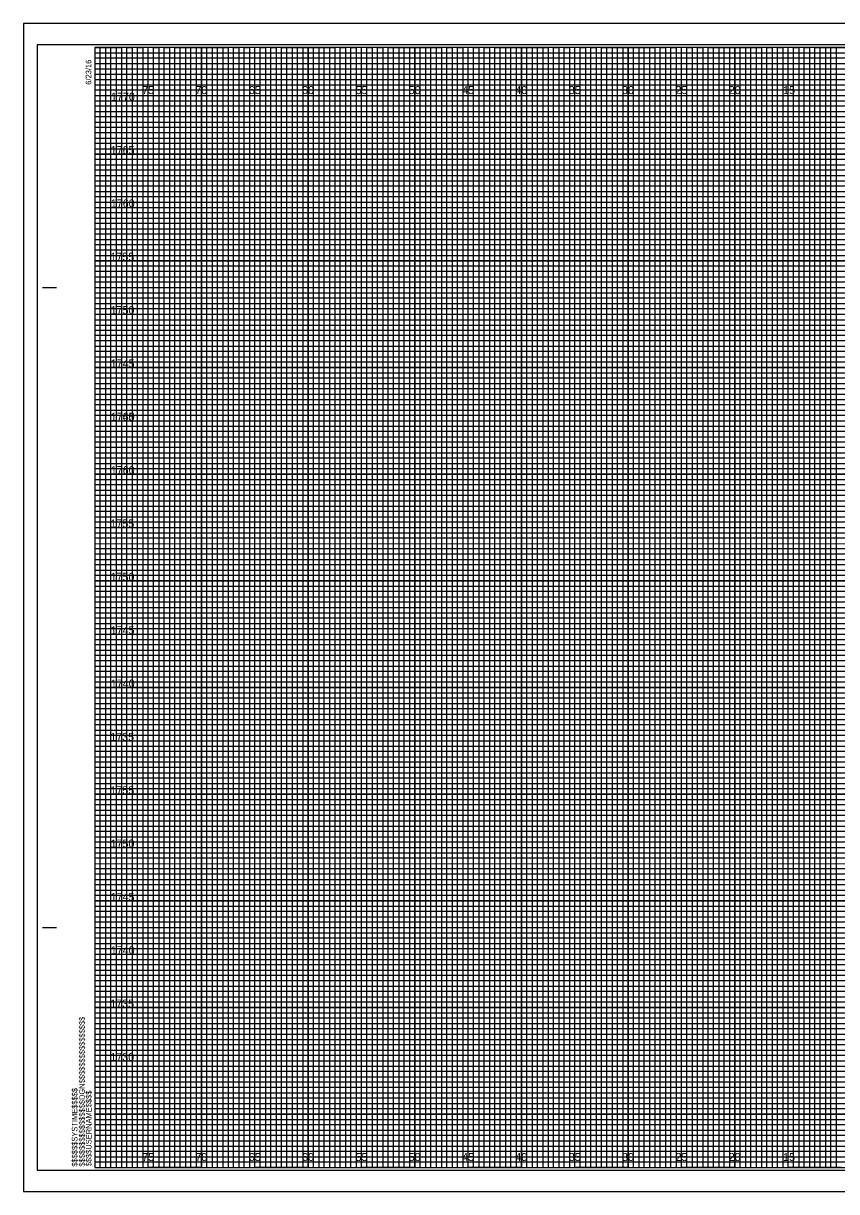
# Model space of a CAD drawing. Extents: x -7 to 162, y -2 to 217.
# Drawn here: x -6.7 to 69.5, y -2.3 to 107.3 of the extents above; entities that cross this region are included whole.
import ezdxf

# ---------------------------------------------------------------- set-up
doc = ezdxf.new("R2010")
doc.units = 0
for name, color, linetype in [('Raster_Level_0', 7, 'Continuous'), ('Scratch_Level_3', 7, 'Continuous'), ('Sheet Cross Section CELL', 7, 'Continuous'), ('Sheet Cross Section Grid Major CELL', 7, 'Continuous'), ('Sheet Cross Section Grid Middle CELL', 7, 'Continuous'), ('Sheet Cross Section Grid Minor 1 CELL', 7, 'Continuous'), ('Sheet Cross Section Grid Minor 2 CELL', 7, 'Continuous'), ('Sheet Cutting Line CELL', 7, 'Continuous'), ('Sheet DOT Grid CELL', 7, 'Continuous'), ('Sheet Plot Border Inside CELL', 7, 'Continuous'), ('Sheet Plot Border Outside CELL', 7, 'Continuous')]:
    doc.layers.add(name, color=color, linetype=linetype)

msp = doc.modelspace()

# ---------------------------------------------------------------- linework, layer by layer
at = {"layer": 'Sheet Cross Section CELL'}
for p, q in [((-4.9, 82.5), (-3.65, 82.5)), ((-4.85, 82.5), (-3.6, 82.5)), ((-4.9, 22.5), (-3.65, 22.5)), ((-4.85, 22.5), (-3.6, 22.5)), ((0, 0), (0, 0)), ((0, 0), (0, 0)), ((0, 0), (0, 0)), ((0, 0), (0, 0)), ((0, 0), (0, 0)), ((0, 0), (0, 0)), ((0, 0), (0, 0))]:
    msp.add_line(p, q, dxfattribs=at)
msp.add_lwpolyline([(160, 105), (0, 105), (0, 0), (160, 0)], close=True, dxfattribs=at)
at = {"layer": 'Sheet Cross Section Grid Major CELL'}
for p, q in [((5, 105), (0, 105)), ((5, 0), (5, 105)), ((15, 105), (10, 105)), ((10, 105), (10, 0)), ((15, 0), (15, 105)), ((25, 105), (20, 105)), ((20, 105), (20, 0)), ((25, 0), (25, 105)), ((35, 105), (30, 105)), ((30, 105), (30, 0)), ((35, 0), (35, 105)), ((45, 105), (40, 105)), ((40, 105), (40, 0)), ((45, 0), (45, 105)), ((55, 105), (50, 105)), ((50, 105), (50, 0)), ((55, 0), (55, 105)), ((65, 105), (60, 105)), ((60, 105), (60, 0)), ((65, 0), (65, 105)), ((10, 0), (5, 0)), ((20, 0), (15, 0)), ((30, 0), (25, 0)), ((40, 0), (35, 0)), ((50, 0), (45, 0)), ((60, 0), (55, 0)), ((70, 0), (65, 0))]:
    msp.add_line(p, q, dxfattribs=at)
for points in [[(0, 100), (160, 100), (160, 95), (0, 95)], [(0, 90), (160, 90), (160, 85), (0, 85)], [(0, 80), (160, 80), (160, 75), (0, 75)], [(0, 70), (160, 70), (160, 65), (0, 65)], [(0, 60), (160, 60), (160, 55), (0, 55)], [(0, 50), (160, 50), (160, 45), (0, 45)], [(0, 40), (160, 40), (160, 35), (0, 35)], [(0, 30), (160, 30), (160, 25), (0, 25)], [(0, 20), (160, 20), (160, 15), (0, 15)], [(0, 10), (160, 10), (160, 5), (0, 5)]]:
    msp.add_lwpolyline(points, dxfattribs=at)
at = {"layer": 'Sheet Cross Section Grid Middle CELL'}
for points in [[(0, 105), (2.5, 105), (2.5, 0), (7.5, 0), (7.5, 105), (12.5, 105), (12.5, 0), (17.5, 0), (17.5, 105), (22.5, 105), (22.5, 0), (27.5, 0), (27.5, 105), (32.5, 105), (32.5, 0), (37.5, 0), (37.5, 105), (42.5, 105), (42.5, 0), (47.5, 0), (47.5, 105), (52.5, 105), (52.5, 0), (57.5, 0), (57.5, 105), (62.5, 105), (62.5, 0), (67.5, 0), (67.5, 105), (72.5, 105)], [(0, 102.5), (137.5, 102.5)], [(0, 92.5), (160, 92.5), (160, 97.5), (0, 97.5)], [(0, 82.5), (160, 82.5), (160, 87.5), (0, 87.5)], [(0, 72.5), (160, 72.5), (160, 77.5), (0, 77.5)], [(0, 62.5), (160, 62.5), (160, 67.5), (0, 67.5)], [(0, 52.5), (160, 52.5), (160, 57.5), (0, 57.5)], [(0, 42.5), (160, 42.5), (160, 47.5), (0, 47.5)], [(0, 32.5), (160, 32.5), (160, 37.5), (0, 37.5)], [(0, 22.5), (160, 22.5), (160, 27.5), (0, 27.5)], [(0, 12.5), (160, 12.5), (160, 17.5), (0, 17.5)], [(0, 2.5), (160, 2.5), (160, 7.5), (0, 7.5)]]:
    msp.add_lwpolyline(points, dxfattribs=at)
at = {"layer": 'Sheet Cross Section Grid Minor 1 CELL'}
for p, q in [((0, 104.5), (130, 104.5)), ((130, 103.99), (0, 103.99)), ((0, 103.99), (0, 103.5)), ((0, 103.5), (130, 103.5)), ((130, 102.95), (0, 102.95)), ((0, 102.95), (0, 102)), ((0, 102), (160, 102))]:
    msp.add_line(p, q, dxfattribs=at)
for points in [[(0, 101.5), (135, 101.5), (160, 101.5), (160, 101), (0, 101)], [(0, 100.5), (160, 100.5), (160, 99.5), (0, 99.5)], [(0, 99), (160, 99), (160, 98.5), (0, 98.49)], [(0, 98), (160, 98), (160, 97), (0, 97)], [(0, 96.5), (160, 96.5), (160, 96), (0, 96)], [(0, 95.5), (160, 95.5), (160, 94.5), (0, 94.5)], [(0, 94), (160, 94), (160, 93.5), (0, 93.5)], [(0, 93), (160, 93), (160, 92), (0, 92)], [(0, 91.5), (160, 91.5), (160, 91), (0, 91)], [(0, 90.5), (160, 90.5), (160, 89.5), (0, 89.5)], [(0, 89), (160, 89), (160, 88.5), (0, 88.5)], [(0, 88), (160, 88), (160, 86.98), (160, 86.5), (160, 86), (0, 86)], [(0, 87), (160, 87), (160, 86.5), (0, 86.5)], [(0, 85.5), (160, 85.5), (160, 84.5), (0, 84.52)], [(0, 84.52), (160, 84.5), (160, 84), (0, 84)], [(0, 83.5), (160, 83.5), (160, 83), (0, 83)], [(0, 82), (160, 82), (160, 81.5), (0, 81.5)], [(0, 81), (160, 81), (160, 80.5), (0, 80.5)], [(-0.04, 79.45), (160, 79.45), (160, 78.94), (-0.04, 78.94)], [(0, 78.5), (160, 78.5), (160, 78), (0, 78)], [(0, 77), (160, 77), (160, 76.5), (0, 76.5)], [(0, 76), (160, 76), (160, 75.5), (0, 75.5)], [(0, 74.5), (160, 74.5), (160, 74), (0, 74)], [(0, 73.5), (160, 73.5), (160, 73), (0, 73)], [(0, 72), (160, 72), (160, 71.5), (0, 71.5)], [(0, 71), (160, 71), (160, 70.5), (0, 70.5)], [(0, 69.5), (160, 69.5), (160, 68.99), (0, 69)], [(0, 68.5), (160, 68.5), (160, 68), (0, 68)], [(0, 67), (160, 67), (160, 66.5), (0, 66.5)], [(0, 66), (160, 66), (160, 65.5), (0, 65.5)], [(0, 64.5), (160, 64.5), (160, 64), (0, 64)], [(0, 63.5), (160, 63.5), (160, 63), (0, 63)], [(0, 62), (160, 62), (160, 61.5), (0, 61.5)], [(0, 61), (160, 61), (160, 60.5), (0, 60.5)], [(0, 59.5), (160, 59.5), (160, 59), (0, 59)], [(0, 58.5), (160.03, 58.45), (160, 58), (0, 58)], [(0, 57), (160, 57), (160, 56.5), (0, 56.5)], [(0, 56), (160, 56), (160, 55.5), (0, 55.5)], [(0, 54.5), (160, 54.5), (160, 54), (0, 54)], [(0, 53.5), (160, 53.5), (160, 53), (0, 53)], [(0, 52), (160, 52), (160, 51.5), (0, 51.5)], [(0, 51), (160, 51), (160, 50.5), (0, 50.5)], [(0, 49.5), (160, 49.5), (160, 49), (0, 49)], [(0, 48.5), (160, 48.5), (160, 48), (0, 48)], [(0, 47), (160, 47), (160, 46.5), (0, 46.5)], [(0, 46), (160, 46), (160, 45.5), (0, 45.5)], [(0, 44.5), (160, 44.5), (160, 44), (0, 44)], [(0, 43.5), (160, 43.5), (160, 43), (0, 43)], [(0, 42), (160, 42), (160, 41.5), (0, 41.5)], [(0, 41), (160, 41), (160, 40.5), (0, 40.5)], [(0, 39.5), (160, 39.5), (160, 38.99), (0, 39)], [(0, 38.5), (160, 38.5), (160, 38), (0, 38)], [(0, 37), (160, 37), (160, 36.5), (0, 36.5)], [(0, 36), (160, 36), (160, 35.5), (0, 35.5)], [(0, 34.5), (160, 34.5), (160, 34), (0, 34)], [(0, 33.5), (160, 33.5), (160, 33), (0, 33)], [(0, 32), (160, 32), (160, 31.5), (0, 31.5)], [(0, 31), (160, 31), (160, 30.5), (0, 30.5)], [(0, 29.5), (160, 29.5), (160, 29), (0, 29)], [(0, 28.5), (160.03, 28.46), (160, 28), (0, 28)], [(0, 27), (160, 27), (160, 26.5), (0, 26.5)], [(0, 26), (160, 26), (160, 25.5), (0, 25.5)], [(0, 24.5), (160, 24.5), (160, 24), (0, 24)], [(0, 23.5), (160, 23.5), (160, 23), (0, 23)], [(0, 22), (160, 22), (160, 21.5), (0, 21.5)], [(0, 21), (160, 21), (160, 20.5), (0, 20.5)], [(0, 19.5), (160, 19.5), (160, 19), (0, 19)], [(0, 18.5), (160, 18.5), (160, 18), (0, 18)], [(0, 17), (160, 17), (160, 16.5), (0, 16.5)], [(0, 16), (160, 16), (160, 15.5), (0, 15.5)], [(0, 14.5), (160, 14.5), (160, 14), (0, 14)], [(0, 13.5), (160, 13.5), (160, 13), (0, 13)], [(0, 12), (160, 12), (160, 11.5), (0, 11.5)], [(0, 11), (160, 11), (160, 10.5), (0, 10.5)], [(0, 9.5), (160, 9.5), (160, 9), (0, 9)], [(0, 8.5), (160, 8.5), (160, 8), (0, 8)], [(0, 7), (160, 7), (160, 6.5), (0, 6.5)], [(0, 6), (160, 6), (160, 5.5), (0, 5.5)], [(0, 4.5), (160, 4.5), (160, 4), (0, 4)], [(0, 3.5), (160, 3.5), (160, 3), (0, 3)], [(0, 2), (160, 2), (160, 1.5), (0, 1.5)], [(0, 1), (160, 1), (160, 0.5), (0, 0.5)]]:
    msp.add_lwpolyline(points, dxfattribs=at)
at = {"layer": 'Sheet Cross Section Grid Minor 2 CELL'}
for points in [[(0, 0), (0.5, 0), (0.5, 105), (1, 105), (1, 0)], [(1, 0), (1.5, 0), (1.5, 105), (2, 105), (2, 0)], [(2.5, 0), (3, 0), (3, 105), (3.5, 105), (3.5, 0)], [(3.5, 0), (4, 0), (4, 105), (4.5, 105), (4.5, 0)], [(5, 0), (5.5, 0), (5.5, 105), (6, 105), (6, 0)], [(6, 0), (6.5, 0), (6.5, 105), (7, 105), (7, 0)], [(7.5, 0), (8, 0), (8, 105), (8.5, 105), (8.5, 0)], [(8.5, 0), (9, 0), (9, 105), (9.5, 105), (9.5, 0)], [(10, 0), (10.5, 0), (10.5, 105), (11, 105), (11, 0)], [(11, 0), (11.5, 0), (11.5, 105), (12, 105), (12, 0)], [(12.5, 0), (13, 0), (13, 105), (13.5, 105), (13.5, 0)], [(13.5, 0), (14, 0), (14, 105), (14.5, 105), (14.5, 0)], [(15, 0), (15.5, 0), (15.5, 105), (16, 105), (16, 0)], [(16, 0), (16.5, 0), (16.5, 105), (17, 105), (17, 0)], [(17.5, 0), (18, 0), (18, 105), (18.5, 105), (18.5, 0)], [(18.5, 0), (19, 0), (19, 105), (19.5, 105), (19.5, 0)], [(20, 0), (20.5, 0), (20.5, 105), (21, 105), (21, 0)], [(21, 0), (21.5, 0), (21.5, 105), (22, 105), (22, 0)], [(22.5, 0), (23, 0), (23, 105), (23.5, 105), (23.5, 0)], [(23.5, 0), (24, 0), (24, 105), (24.5, 105), (24.5, 0)], [(25, 0), (25.5, 0), (25.5, 105), (26, 105), (26, 0)], [(26, 0), (26.5, 0), (26.5, 105), (27, 105), (27, 0)], [(27.5, 0), (28, 0), (28, 105), (28.5, 105), (28.5, 0)], [(28.5, 0), (29, 0), (29, 105), (29.5, 105), (29.5, 0)], [(30, 0), (30.5, 0), (30.5, 105), (31, 105), (31, 0)], [(31, 0), (31.5, 0), (31.5, 105), (32, 105), (32, 0)], [(32.5, 0), (33, 0), (33, 105), (33.5, 105), (33.5, 0)], [(33.5, 0), (34, 0), (34, 105), (34.5, 105), (34.5, 0)], [(35, 0), (35.5, 0), (35.5, 105), (36, 105), (36, 0)], [(36, 0), (36.5, 0), (36.5, 105), (37, 105), (37, 0)], [(37.5, 0), (38, 0), (38, 105), (38.5, 105), (38.5, 0)], [(38.5, 0), (39, 0), (39, 105), (39.5, 105), (39.5, 0)], [(40, 0), (40.5, 0), (40.5, 105), (41, 105), (41, 0)], [(41, 0), (41.5, 0), (41.5, 105), (42, 105), (42, 0)], [(42.5, 0), (43, 0), (43, 105), (43.5, 105), (43.5, 0)], [(43.5, 0), (44, 0), (44, 105), (44.5, 105), (44.5, 0)], [(45, 0), (45.5, 0), (45.5, 105), (46, 105), (46, 0)], [(46, 0), (46.5, 0), (46.5, 105), (47, 105), (47, 0)], [(47.5, 0), (48, 0), (48, 105), (48.5, 105), (48.5, 0)], [(48.5, 0), (49, 0), (49, 105), (49.5, 105), (49.5, 0)], [(50, 0), (50.5, 0), (50.5, 105), (51, 105), (51, 0)], [(51, 0), (51.5, 0), (51.5, 105), (52, 105), (52, 0)], [(52.5, 0), (53, 0), (53, 105), (53.5, 105), (53.5, 0)], [(53.5, 0), (54, 0), (54, 105), (54.5, 105), (54.5, 0)], [(55, 0), (55.5, 0), (55.5, 105), (56, 105), (56, 0)], [(56, 0), (56.5, 0), (56.5, 105), (57, 105), (57, 0)], [(57.5, 0), (58, 0), (58, 105), (58.5, 105), (58.5, 0)], [(58.5, 0), (59, 0), (59, 105), (59.5, 105), (59.5, 0)], [(60, 0), (60.5, 0), (60.5, 105), (61, 105), (61, 0)], [(61, 0), (61.5, 0), (61.5, 105), (62, 105), (62, 0)], [(62.5, 0), (63, 0), (63, 105), (63.5, 105), (63.5, 0)], [(63.5, 0), (64, 0), (64, 105), (64.5, 105), (64.5, 0)], [(65, 0), (65.5, 0), (65.5, 105), (66, 105), (66, 0)], [(66, 0), (66.5, 0), (66.5, 105), (67, 105), (67, 0)], [(67.5, 0), (68, 0), (68, 105), (68.5, 105), (68.5, 0)], [(68.5, 0), (69, 0), (69, 105), (69.5, 105), (69.5, 0)]]:
    msp.add_lwpolyline(points, dxfattribs=at)
at = {"layer": 'Sheet Cutting Line CELL'}
for p, q in [((161.65, 107.25), (-6.7, 107.25)), ((-6.7, 107.25), (-6.7, -2.25)), ((-6.7, -2.25), (161.65, -2.25))]:
    msp.add_line(p, q, dxfattribs=at)
at = {"layer": 'Sheet DOT Grid CELL'}
for p, q in [((5, 0), (5, 105)), ((10, 0), (10, 105)), ((15, 0), (15, 105)), ((20, 0), (20, 105)), ((25, 0), (25, 105)), ((30, 0), (30, 105)), ((35, 0), (35, 105)), ((40, 0), (40, 105)), ((45, 0), (45, 105)), ((50, 0), (50, 105)), ((55, 0), (55, 105)), ((60, 0), (60, 105)), ((65, 0), (65, 105)), ((0, 100), (160, 100)), ((0, 95), (160, 95)), ((0, 90), (160, 90)), ((0, 85), (160, 85)), ((0, 80), (160, 80)), ((0, 75), (160, 75)), ((0, 70), (160, 70)), ((0, 65), (160, 65)), ((0, 60), (160, 60)), ((0, 55), (160, 55)), ((0, 50), (160, 50)), ((0, 45), (160, 45)), ((0, 40), (160, 40)), ((0, 35), (160, 35)), ((0, 30), (160, 30)), ((0, 25), (160, 25)), ((0, 20), (160, 20)), ((0, 15), (160, 15)), ((0, 10), (160, 10)), ((0, 5), (160, 5))]:
    msp.add_line(p, q, dxfattribs=at)
at = {"layer": 'Sheet Plot Border Inside CELL'}
msp.add_lwpolyline([(-5.4, -0.25), (161.2, -0.25), (161.2, 105.25), (-5.4, 105.25)], close=True, dxfattribs=at)
at = {"layer": 'Sheet Plot Border Outside CELL'}
msp.add_lwpolyline([(-6.7, -2.25), (161.65, -2.25), (161.65, 107.25), (-6.7, 107.25)], close=True, dxfattribs=at)

# ---------------------------------------------------------------- texts
at = {"layer": 'Raster_Level_0'}
for s, p in [('75', (4.44, 100.62)), ('70', (9.43, 100.62)), ('65', (14.44, 100.62)), ('60', (19.43, 100.62)), ('55', (24.44, 100.62)), ('50', (29.43, 100.62)), ('45', (34.44, 100.62)), ('40', (39.43, 100.62)), ('35', (44.44, 100.62)), ('30', (49.43, 100.62)), ('25', (54.44, 100.62)), ('20', (59.43, 100.62)), ('15', (64.53, 100.62)), ('75', (4.44, 0.62)), ('70', (9.43, 0.62)), ('65', (14.44, 0.62)), ('60', (19.43, 0.62)), ('55', (24.44, 0.62)), ('50', (29.43, 0.62)), ('45', (34.44, 0.62)), ('40', (39.43, 0.62)), ('35', (44.44, 0.62)), ('30', (49.43, 0.62)), ('25', (54.44, 0.62)), ('20', (59.43, 0.62)), ('15', (64.53, 0.62))]:
    msp.add_text(s, height=0.75, dxfattribs=at).set_placement(p)
at = {"layer": 'Scratch_Level_3'}
for s, p in [('1770', (1.52, 100)), ('1765', (1.49, 95)), ('1760', (1.5, 90)), ('1755', (1.47, 85)), ('1750', (1.48, 80)), ('1745', (1.49, 75)), ('1765', (1.49, 70)), ('1740', (1.5, 70)), ('1760', (1.5, 65)), ('1755', (1.47, 60)), ('1750', (1.48, 55)), ('1745', (1.49, 50)), ('1740', (1.5, 45)), ('1735', (1.45, 40)), ('1755', (1.47, 35)), ('1750', (1.48, 30)), ('1745', (1.49, 25)), ('1740', (1.5, 20)), ('1735', (1.45, 15)), ('1730', (1.46, 10))]:
    msp.add_text(s, height=0.75, dxfattribs=at).set_placement(p)
at = {"layer": 'Sheet Cross Section CELL'}
for s, p in [('6/23/16', (-0.33, 101.5)), ('$$$$$$$$$$$$$$$$DGN$$$$$$$$$$$$$$$$', (-0.94, 0.09)), ('$$$$$$SYSTIME$$$$$', (-1.63, 0.09)), ('$$$$USERNAME$$$$', (-0.31, 0.12))]:
    msp.add_text(s, height=0.525, rotation=90, dxfattribs=at).set_placement(p)

doc.saveas('drawing.dxf')
